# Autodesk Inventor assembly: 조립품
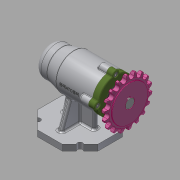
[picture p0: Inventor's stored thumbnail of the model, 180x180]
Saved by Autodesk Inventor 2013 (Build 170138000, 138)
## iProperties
Created: 2021-01
Part Number: 조립품
Document SubType Name: Assembly
Designer: Administrator
Author: Administrator
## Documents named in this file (12)
- C:\Users\Administrator\Desktop\710106V1040\조립품.iam
- C:\Users\Administrator\Desktop\710106V1040\본체.ipt
- C:\Users\Administrator\Desktop\710106V1040\멈춤나사 M3.ipt
- C:\Users\Administrator\Desktop\710106V1040\베어링 6004.ipt
- C:\Users\Administrator\Desktop\710106V1040\베어링 51202.ipt
- C:\Users\Administrator\Desktop\710106V1040\볼트 M4.ipt
- C:\Users\Administrator\Desktop\710106V1040\스프로킷.ipt
- C:\Users\Administrator\Desktop\710106V1040\어댑터슬리브.ipt
- C:\Users\Administrator\Desktop\710106V1040\오일 실.ipt
- C:\Users\Administrator\Desktop\710106V1040\축.ipt
- C:\Users\Administrator\Desktop\710106V1040\커버.ipt
- C:\Users\Administrator\Desktop\710106V1040\키 5 x 5 x 14.ipt
